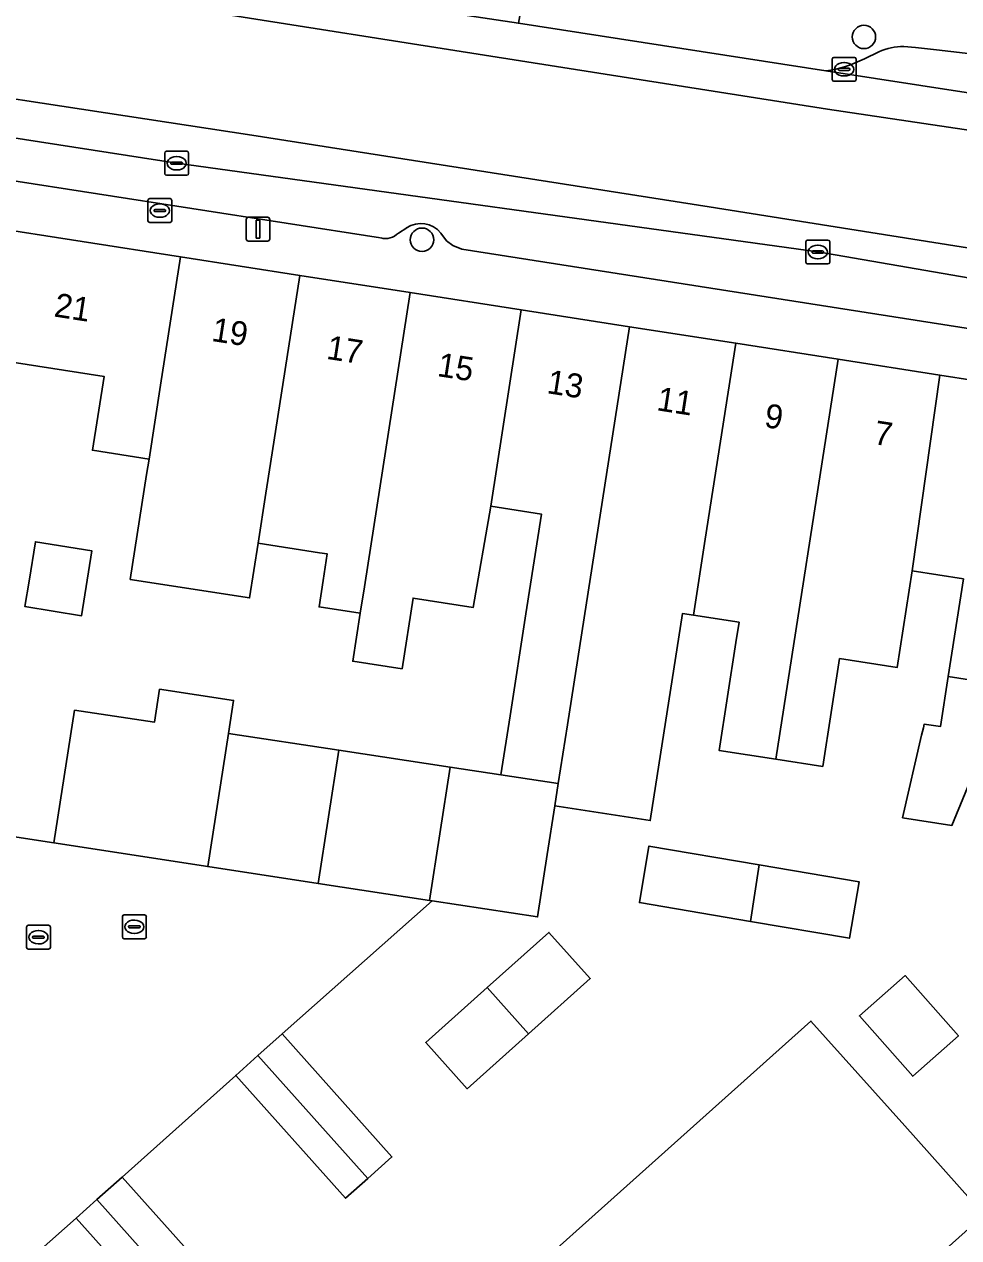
# Model space of a CAD drawing. Extents: x 162172 to 163187, y 382874 to 383685.
# Drawn here: x 162633.7 to 162672.8, y 383280.9 to 383331.7 of the extents above; entities that cross this region are included whole.
import ezdxf

# ---------------------------------------------------------------- set-up
doc = ezdxf.new("R2010")
doc.units = 0
for name, color, linetype in [('IMGEO_Boom', 7, 'Continuous'), ('IMGEO_Brandkraan', 7, 'Continuous'), ('IMGEO_Erf', 7, 'Continuous'), ('IMGEO_Kolk', 7, 'Continuous'), ('IMGEO_Lichtmast', 7, 'Continuous'), ('IMGEO_Pand', 7, 'Continuous'), ('IMGEO_Pand_nummerreeks', 7, 'Continuous'), ('IMGEO_Parkeervlak_open', 7, 'Continuous'), ('IMGEO_Rijbaan_lokaal_gesloten', 7, 'Continuous'), ('IMGEO_Rijbaan_lokaal_open', 7, 'Continuous'), ('IMGEO_Rioolput', 7, 'Continuous'), ('IMGEO_Voetpad_open', 7, 'Continuous')]:
    doc.layers.add(name, color=color, linetype=linetype)

msp = doc.modelspace()

# ---------------------------------------------------------------- linework, layer by layer
at = {"layer": 'IMGEO_Boom'}
for centre in [(162668.827, 383331.156), (162650.322, 383322.668)]:
    msp.add_circle(centre, 0.489, dxfattribs=at)
at = {"layer": 'IMGEO_Brandkraan'}
for p, q in [((162638.844, 383323.463), (162638.844, 383324.315)), ((162638.919, 383324.389), (162639.771, 383324.389)), ((162639.332, 383324.169), (162639.357, 383324.169)), ((162639.845, 383324.315), (162639.845, 383323.463)), ((162639.103, 383323.883), (162639.103, 383323.895)), ((162639.541, 383323.846), (162639.143, 383323.846)), ((162639.146, 383323.932), (162639.544, 383323.932)), ((162639.587, 383323.895), (162639.587, 383323.883)), ((162639.771, 383323.389), (162638.919, 383323.389)), ((162639.355, 383323.609), (162639.33, 383323.609))]:
    msp.add_line(p, q, dxfattribs=at)
for points in [[(162638.844, 383323.463), (162638.844, 383324.315)], [(162638.919, 383324.389), (162639.771, 383324.389)], [(162639.845, 383324.315), (162639.845, 383323.463)], [(162639.771, 383323.389), (162638.919, 383323.389)]]:
    msp.add_lwpolyline(points, dxfattribs=at)
for centre, radius, start, end in [((162638.921, 383324.313), 0.0765, 91.552, 178.448), ((162638.921, 383324.313), 0.0765, 91.552, 178.448), ((162639.769, 383324.313), 0.0765, 1.552, 88.448), ((162639.769, 383324.313), 0.0765, 1.552, 88.448), ((162639.143, 383323.892), 0.0403, 85.8775, 175.7526), ((162639.14, 383323.882), 0.0366, 178.938, 274.7102), ((162639.544, 383323.889), 0.043, 264.8664, 352.4533), ((162639.548, 383323.894), 0.0386, 1.7309, 96.639), ((162638.921, 383323.465), 0.0765, 181.552, 268.448), ((162638.921, 383323.465), 0.0765, 181.552, 268.448), ((162639.769, 383323.465), 0.0765, 271.552, 358.448), ((162639.769, 383323.465), 0.0765, 271.552, 358.448)]:
    msp.add_arc(centre, radius, start, end, dxfattribs=at)
for centre, major_axis, ratio, start_param, end_param in [((162639.331, 383323.889), (-0.387, 0.002), 0.722429, 4.712389, 7.853982), ((162639.356, 383323.889), (-0.39, 0.002), 0.717154, 1.570796, 4.712389)]:
    msp.add_ellipse(centre, major_axis=major_axis, ratio=ratio, start_param=start_param, end_param=end_param, dxfattribs=at)
at = {"layer": 'IMGEO_Erf'}
for points in [[(162631.523, 383297.936), (162634.907, 383297.419), (162635.772, 383302.977), (162639.117, 383302.47), (162639.333, 383303.854), (162642.432, 383303.384), (162642.217, 383302), (162646.844, 383301.3), (162651.499, 383300.594), (162653.623, 383300.272), (162654.007, 383302.742), (162654.672, 383307.015), (162655.321, 383311.187), (162653.2, 383311.517), (162652.468, 383307.28), (162649.948, 383307.672), (162649.487, 383304.708), (162647.425, 383305.028), (162647.737, 383307.034), (162646.012, 383307.303), (162646.183, 383308.404), (162646.357, 383309.517), (162646.024, 383309.569), (162643.457, 383309.968), (162643.1, 383307.674), (162638.109, 383308.451), (162638.792, 383312.839), (162638.892, 383313.48), (162636.521, 383313.858), (162637.013, 383316.947), (162632.069, 383317.716)], [(162674.08, 383301.973), (162672.512, 383298.155), (162670.441, 383298.478), (162671.243, 383301.926), (162671.316, 383302.239), (162671.353, 383302.398), (162672.027, 383302.293), (162672.353, 383304.387), (162672.989, 383308.47), (162670.841, 383308.804), (162670.213, 383304.762), (162667.807, 383305.136), (162667.105, 383300.621), (162665.136, 383300.927), (162662.764, 383301.296), (162663.466, 383305.811), (162663.598, 383306.659), (162661.683, 383306.957), (162661.23, 383307.027), (162659.878, 383298.358), (162655.881, 383298.979), (162655.569, 383296.943), (162655.162, 383294.323), (162650.75, 383294.997), (162644.466, 383289.424), (162649.063, 383284.282), (162648.053, 383283.379), (162647.121, 383282.545), (162642.523, 383287.687), (162637.762, 383283.434), (162642.37, 383278.28)], [(162640.451, 383276.564), (162635.843, 383281.717), (162632.163, 383278.465)]]:
    msp.add_lwpolyline(points, dxfattribs=at)
for points in [[(162633.867, 383308.374), (162634.137, 383310.028), (162636.504, 383309.641), (162636.06, 383306.924), (162633.694, 383307.311)], [(162659.426, 383294.924), (162659.826, 383297.287), (162664.446, 383296.504), (162668.621, 383295.797), (162668.221, 383293.434), (162664.076, 383294.136)], [(162657.367, 383291.74), (162654.784, 383289.43), (162652.212, 383287.13), (162650.478, 383289.068), (162653.05, 383291.368), (162655.633, 383293.678)], [(162668.637, 383290.177), (162670.546, 383291.87), (162672.78, 383289.35), (162670.871, 383287.657)], [(162666.609, 383289.967), (162670.532, 383285.58), (162673.865, 383281.853), (162650.074, 383260.577), (162642.818, 383268.691), (162646.546, 383272.025)]]:
    msp.add_lwpolyline(points, close=True, dxfattribs=at)
at = {"layer": 'IMGEO_Kolk'}
for p, q in [((162667.572, 383330.302), (162668.424, 383330.302)), ((162667.497, 383329.376), (162667.497, 383330.228)), ((162667.756, 383329.796), (162667.756, 383329.808)), ((162668.194, 383329.759), (162667.796, 383329.759)), ((162667.799, 383329.845), (162668.197, 383329.845)), ((162667.985, 383330.082), (162668.01, 383330.082)), ((162668.24, 383329.808), (162668.24, 383329.796)), ((162668.498, 383330.228), (162668.498, 383329.376)), ((162668.424, 383329.302), (162667.572, 383329.302)), ((162668.008, 383329.522), (162667.983, 383329.522)), ((162639.549, 383325.443), (162639.549, 383326.295)), ((162639.624, 383326.369), (162640.476, 383326.369)), ((162640.55, 383326.295), (162640.55, 383325.443)), ((162639.808, 383325.863), (162639.808, 383325.875)), ((162640.246, 383325.826), (162639.848, 383325.826)), ((162639.851, 383325.912), (162640.249, 383325.912)), ((162640.037, 383326.149), (162640.062, 383326.149)), ((162640.292, 383325.875), (162640.292, 383325.863)), ((162640.476, 383325.369), (162639.624, 383325.369)), ((162640.06, 383325.589), (162640.035, 383325.589)), ((162666.469, 383322.655), (162667.321, 383322.655)), ((162666.394, 383321.729), (162666.394, 383322.581)), ((162666.653, 383322.149), (162666.653, 383322.161)), ((162667.091, 383322.112), (162666.693, 383322.112)), ((162666.696, 383322.198), (162667.094, 383322.198)), ((162666.882, 383322.435), (162666.907, 383322.435)), ((162667.137, 383322.161), (162667.137, 383322.149)), ((162667.395, 383322.581), (162667.395, 383321.729)), ((162667.321, 383321.655), (162666.469, 383321.655)), ((162666.905, 383321.875), (162666.88, 383321.875)), ((162637.778, 383293.485), (162637.778, 383294.337)), ((162637.853, 383294.411), (162638.705, 383294.411)), ((162638.266, 383294.191), (162638.291, 383294.191)), ((162638.779, 383294.337), (162638.779, 383293.485)), ((162638.037, 383293.905), (162638.037, 383293.917)), ((162638.475, 383293.868), (162638.077, 383293.868)), ((162638.08, 383293.954), (162638.478, 383293.954)), ((162638.521, 383293.917), (162638.521, 383293.905)), ((162638.705, 383293.411), (162637.853, 383293.411)), ((162638.289, 383293.631), (162638.264, 383293.631))]:
    msp.add_line(p, q, dxfattribs=at)
for points in [[(162667.572, 383330.302), (162668.424, 383330.302)], [(162667.497, 383329.376), (162667.497, 383330.228)], [(162668.498, 383330.228), (162668.498, 383329.376)], [(162668.424, 383329.302), (162667.572, 383329.302)], [(162639.549, 383325.443), (162639.549, 383326.295)], [(162639.624, 383326.369), (162640.476, 383326.369)], [(162640.55, 383326.295), (162640.55, 383325.443)], [(162640.476, 383325.369), (162639.624, 383325.369)], [(162666.469, 383322.655), (162667.321, 383322.655)], [(162666.394, 383321.729), (162666.394, 383322.581)], [(162667.395, 383322.581), (162667.395, 383321.729)], [(162667.321, 383321.655), (162666.469, 383321.655)], [(162637.778, 383293.485), (162637.778, 383294.337)], [(162637.853, 383294.411), (162638.705, 383294.411)], [(162638.779, 383294.337), (162638.779, 383293.485)], [(162638.705, 383293.411), (162637.853, 383293.411)]]:
    msp.add_lwpolyline(points, dxfattribs=at)
for centre, radius, start, end in [((162667.574, 383330.226), 0.0765, 91.552, 178.448), ((162667.574, 383330.226), 0.0765, 91.552, 178.448), ((162668.422, 383330.226), 0.0765, 1.552, 88.448), ((162668.422, 383330.226), 0.0765, 1.552, 88.448), ((162667.796, 383329.805), 0.0403, 85.8775, 175.7526), ((162667.793, 383329.795), 0.0366, 178.938, 274.7102), ((162668.197, 383329.802), 0.043, 264.8664, 352.4533), ((162668.201, 383329.807), 0.0386, 1.7309, 96.639), ((162667.574, 383329.378), 0.0765, 181.552, 268.448), ((162667.574, 383329.378), 0.0765, 181.552, 268.448), ((162668.422, 383329.378), 0.0765, 271.552, 358.448), ((162668.422, 383329.378), 0.0765, 271.552, 358.448), ((162639.626, 383326.293), 0.0765, 91.552, 178.448), ((162639.626, 383326.293), 0.0765, 91.552, 178.448), ((162640.474, 383326.293), 0.0765, 1.552, 88.448), ((162640.474, 383326.293), 0.0765, 1.552, 88.448), ((162639.848, 383325.872), 0.0403, 85.8775, 175.7526), ((162639.845, 383325.862), 0.0366, 178.938, 274.7102), ((162640.249, 383325.869), 0.043, 264.8664, 352.4533), ((162640.253, 383325.874), 0.0386, 1.7309, 96.639), ((162639.626, 383325.445), 0.0765, 181.552, 268.448), ((162639.626, 383325.445), 0.0765, 181.552, 268.448), ((162640.474, 383325.445), 0.0765, 271.552, 358.448), ((162640.474, 383325.445), 0.0765, 271.552, 358.448), ((162666.471, 383322.579), 0.0765, 91.552, 178.448), ((162666.471, 383322.579), 0.0765, 91.552, 178.448), ((162667.319, 383322.579), 0.0765, 1.552, 88.448), ((162667.319, 383322.579), 0.0765, 1.552, 88.448), ((162666.693, 383322.158), 0.0403, 85.8775, 175.7526), ((162666.69, 383322.148), 0.0366, 178.938, 274.7102), ((162667.094, 383322.155), 0.043, 264.8664, 352.4533), ((162667.098, 383322.16), 0.0386, 1.7309, 96.639), ((162666.471, 383321.731), 0.0765, 181.552, 268.448), ((162666.471, 383321.731), 0.0765, 181.552, 268.448), ((162667.319, 383321.731), 0.0765, 271.552, 358.448), ((162667.319, 383321.731), 0.0765, 271.552, 358.448), ((162637.855, 383294.335), 0.0765, 91.552, 178.448), ((162637.855, 383294.335), 0.0765, 91.552, 178.448), ((162638.703, 383294.335), 0.0765, 1.552, 88.448), ((162638.703, 383294.335), 0.0765, 1.552, 88.448), ((162638.077, 383293.914), 0.0403, 85.8775, 175.7526), ((162638.074, 383293.904), 0.0366, 178.938, 274.7102), ((162638.478, 383293.911), 0.043, 264.8664, 352.4533), ((162638.482, 383293.916), 0.0386, 1.7309, 96.639), ((162637.855, 383293.487), 0.0765, 181.552, 268.448), ((162637.855, 383293.487), 0.0765, 181.552, 268.448), ((162638.703, 383293.487), 0.0765, 271.552, 358.448), ((162638.703, 383293.487), 0.0765, 271.552, 358.448)]:
    msp.add_arc(centre, radius, start, end, dxfattribs=at)
for centre, major_axis, ratio, start_param, end_param in [((162667.984, 383329.802), (-0.387, 0.002), 0.722429, 4.712389, 7.853982), ((162668.009, 383329.802), (-0.39, 0.002), 0.717154, 1.570796, 4.712389), ((162640.036, 383325.869), (-0.387, 0.002), 0.722429, 4.712389, 7.853982), ((162640.061, 383325.869), (-0.39, 0.002), 0.717154, 1.570796, 4.712389), ((162666.881, 383322.155), (-0.387, 0.002), 0.722429, 4.712389, 7.853982), ((162666.906, 383322.155), (-0.39, 0.002), 0.717154, 1.570796, 4.712389), ((162638.265, 383293.911), (-0.387, 0.002), 0.722429, 4.712389, 7.853982), ((162638.29, 383293.911), (-0.39, 0.002), 0.717154, 1.570796, 4.712389)]:
    msp.add_ellipse(centre, major_axis=major_axis, ratio=ratio, start_param=start_param, end_param=end_param, dxfattribs=at)
at = {"layer": 'IMGEO_Lichtmast'}
for p, q in [((162642.959, 383322.71), (162642.959, 383323.51)), ((162642.959, 383323.51), (162642.959, 383322.71)), ((162643.059, 383323.61), (162643.849, 383323.61)), ((162643.849, 383323.61), (162643.059, 383323.61)), ((162643.949, 383323.51), (162643.949, 383322.71)), ((162643.949, 383322.71), (162643.949, 383323.51)), ((162643.849, 383322.61), (162643.059, 383322.61)), ((162643.059, 383322.61), (162643.849, 383322.61))]:
    msp.add_line(p, q, dxfattribs=at)
msp.add_lwpolyline([(162643.379, 383323.485), (162643.529, 383323.485), (162643.529, 383322.735), (162643.379, 383322.735), (162643.379, 383323.485)], dxfattribs=at)
for centre, start, end in [((162643.059, 383323.51), 90, 180), ((162643.059, 383323.51), 90, 180), ((162643.849, 383323.51), 0, 90), ((162643.849, 383323.51), 360, 90), ((162643.059, 383322.71), 180, 270), ((162643.059, 383322.71), 180, 270), ((162643.849, 383322.71), 270, 0), ((162643.849, 383322.71), 270, 0)]:
    msp.add_arc(centre, 0.1, start, end, dxfattribs=at)
at = {"layer": 'IMGEO_Pand'}
for points in [[(162640.21, 383321.951), (162631.965, 383323.234), (162631.649, 383323.283), (162630.867, 383317.903), (162631.183, 383317.854), (162632.069, 383317.716), (162637.013, 383316.947), (162636.521, 383313.858), (162638.892, 383313.48), (162639.374, 383316.579)], [(162645.201, 383321.175), (162640.21, 383321.951), (162639.374, 383316.579), (162638.892, 383313.48), (162638.792, 383312.839), (162638.109, 383308.451), (162643.1, 383307.674), (162643.457, 383309.968), (162643.783, 383312.062), (162643.976, 383313.301)], [(162649.828, 383320.455), (162645.201, 383321.175), (162643.976, 383313.301), (162643.783, 383312.062), (162643.457, 383309.968), (162646.024, 383309.569), (162646.357, 383309.517), (162646.183, 383308.404), (162646.012, 383307.303), (162647.737, 383307.034), (162647.909, 383308.136)], [(162654.479, 383319.731), (162649.828, 383320.455), (162647.909, 383308.136), (162647.737, 383307.034), (162647.425, 383305.028), (162649.487, 383304.708), (162649.948, 383307.672), (162652.468, 383307.28), (162653.2, 383311.517)], [(162659.009, 383319.026), (162654.479, 383319.731), (162653.2, 383311.517), (162655.321, 383311.187), (162654.672, 383307.015), (162654.007, 383302.742), (162653.623, 383300.272), (162656.023, 383299.909), (162656.415, 383302.367)], [(162662.178, 383310.134), (162663.456, 383318.334), (162659.009, 383319.026), (162656.415, 383302.367), (162656.023, 383299.909), (162655.881, 383298.979), (162659.878, 383298.358), (162661.23, 383307.027), (162661.683, 383306.957)], [(162665.136, 383300.927), (162667.748, 383317.667), (162663.456, 383318.334), (162662.178, 383310.134), (162661.683, 383306.957), (162663.598, 383306.659), (162663.466, 383305.811), (162662.764, 383301.296)], [(162665.136, 383300.927), (162667.105, 383300.621), (162667.807, 383305.136), (162670.213, 383304.762), (162670.841, 383308.804), (162672.001, 383317.005), (162667.748, 383317.667)], [(162676.322, 383316.333), (162672.001, 383317.005), (162670.841, 383308.804), (162672.989, 383308.47), (162672.353, 383304.387), (162674.407, 383304.066)], [(162633.867, 383308.374), (162633.694, 383307.311), (162636.06, 383306.924), (162636.504, 383309.641), (162634.137, 383310.028)], [(162674.109, 383302.16), (162674.407, 383304.066), (162672.353, 383304.387), (162672.027, 383302.293), (162671.353, 383302.398), (162671.316, 383302.239), (162671.243, 383301.926), (162670.441, 383298.478), (162672.512, 383298.155), (162674.08, 383301.973)], [(162642.217, 383302), (162642.432, 383303.384), (162639.333, 383303.854), (162639.117, 383302.47), (162635.772, 383302.977), (162634.907, 383297.419), (162641.351, 383296.434)], [(162645.976, 383295.727), (162646.844, 383301.3), (162642.217, 383302), (162641.351, 383296.434)], [(162650.631, 383295.015), (162651.499, 383300.594), (162646.844, 383301.3), (162645.976, 383295.727)], [(162655.881, 383298.979), (162656.023, 383299.909), (162653.623, 383300.272), (162651.499, 383300.594), (162650.631, 383295.015), (162650.75, 383294.997), (162655.162, 383294.323), (162655.569, 383296.943)], [(162664.446, 383296.504), (162659.826, 383297.287), (162659.426, 383294.924), (162664.076, 383294.136)], [(162664.076, 383294.136), (162668.221, 383293.434), (162668.621, 383295.797), (162664.446, 383296.504)], [(162654.784, 383289.43), (162657.367, 383291.74), (162655.633, 383293.678), (162653.05, 383291.368)], [(162670.871, 383287.657), (162672.78, 383289.35), (162670.546, 383291.87), (162668.637, 383290.177)], [(162654.784, 383289.43), (162653.05, 383291.368), (162650.478, 383289.068), (162652.212, 383287.13)], [(162670.532, 383285.58), (162666.609, 383289.967), (162646.546, 383272.025), (162642.818, 383268.691), (162650.074, 383260.577), (162673.865, 383281.853)], [(162643.454, 383288.52), (162648.053, 383283.379), (162649.063, 383284.282), (162644.466, 383289.424)], [(162643.454, 383288.52), (162642.523, 383287.687), (162647.121, 383282.545), (162648.053, 383283.379)], [(162636.707, 383282.49), (162641.316, 383277.338), (162642.37, 383278.28), (162637.762, 383283.434)], [(162636.707, 383282.49), (162635.843, 383281.717), (162640.451, 383276.564), (162641.316, 383277.338)]]:
    msp.add_lwpolyline(points, close=True, dxfattribs=at)
at = {"layer": 'IMGEO_Parkeervlak_open'}
for points in [[(162681.525, 383329.352), (162678.105, 383329.885), (162671.858, 383330.613), (162670.982, 383330.717), (162670.498, 383330.752)], [(162669.456, 383330.536), (162668.843, 383330.245)], [(162694.423, 383317.323), (162690.471, 383318.089), (162666.895, 383322.156), (162640.05, 383325.87), (162617.849, 383329.326), (162614.538, 383329.866)], [(162667.234, 383329.74), (162695.256, 383325.416)], [(162632.784, 383325.209), (162648.591, 383322.748)], [(162649.335, 383322.95), (162649.68, 383323.161)], [(162651.106, 383322.943), (162651.352, 383322.618), (162651.606, 383322.432), (162651.984, 383322.267), (162675.159, 383318.642), (162675.566, 383318.718), (162675.894, 383318.855), (162676.175, 383319.078)]]:
    msp.add_lwpolyline(points, dxfattribs=at)
for centre, radius, start, end in [((162670.427, 383328.472), 2.281, 88.221, 115.2013), ((162666.579, 383334.644), 4.948, 277.6126, 297.2373), ((162650.278, 383322.303), 1.046, 37.7242, 124.8922), ((162648.795, 383323.469), 0.749, 254.2345, 316.1453)]:
    msp.add_arc(centre, radius, start, end, dxfattribs=at)
at = {"layer": 'IMGEO_Rijbaan_lokaal_gesloten'}
for points in [[(162701.209, 383324.364), (162695.256, 383325.416), (162667.234, 383329.74), (162654.358, 383331.729), (162650.713, 383332.282), (162613.69, 383338.058), (162613.319, 383338.115), (162605.204, 383339.371), (162601.788, 383339.9), (162574.971, 383344.078), (162574.184, 383344.194), (162573.598, 383344.329), (162573.305, 383344.396)], [(162572.334, 383336.354), (162582.593, 383334.79), (162596.519, 383332.638), (162599.695, 383332.15), (162604.062, 383331.476), (162608.129, 383330.849), (162614.538, 383329.866), (162617.849, 383329.326), (162640.05, 383325.87), (162666.895, 383322.156), (162690.471, 383318.089), (162694.423, 383317.323)], [(162759.102, 383279.436), (162751.245, 383288.934), (162744.614, 383296.969), (162741.887, 383300.164), (162738.772, 383303.437), (162735.656, 383306.164), (162728.412, 383311.307), (162722.803, 383314.892), (162719.766, 383316.606), (162716.105, 383318.242), (162707.381, 383321.359), (162706.089, 383321.777), (162704.23, 383322.378), (162698.267, 383323.385), (162686.155, 383325.334), (162667.305, 383328.139), (162627.21, 383334.45)], [(162627.21, 383334.45), (162667.305, 383328.139), (162686.155, 383325.334), (162698.267, 383323.385), (162704.23, 383322.378), (162706.089, 383321.777), (162707.381, 383321.359), (162716.105, 383318.242), (162719.766, 383316.606), (162722.803, 383314.892), (162728.412, 383311.307), (162735.656, 383306.164), (162738.772, 383303.437), (162741.887, 383300.164), (162744.614, 383296.969), (162751.245, 383288.934), (162759.102, 383279.436)], [(162707.088, 383314.928), (162701.541, 383316.806), (162700.737, 383317.078), (162700.292, 383317.242), (162697.78, 383318.084), (162693.028, 383319.097), (162684.675, 383320.5), (162662.339, 383324.046), (162643.197, 383327.047), (162623.802, 383330.008)], [(162623.802, 383330.008), (162643.197, 383327.047), (162662.339, 383324.046), (162684.675, 383320.5), (162693.028, 383319.097), (162697.78, 383318.084), (162700.292, 383317.242), (162700.737, 383317.078), (162701.541, 383316.806), (162707.088, 383314.928), (162713.047, 383312.279), (162718.051, 383309.824), (162725.217, 383305.07), (162729.268, 383302.265), (162732.618, 383299.46), (162735.188, 383297.122), (162737.681, 383294.706), (162741.264, 383290.81), (162746.988, 383284.773), (162754.973, 383275.848)]]:
    msp.add_lwpolyline(points, dxfattribs=at)
at = {"layer": 'IMGEO_Rijbaan_lokaal_open'}
msp.add_lwpolyline([(162632.163, 383278.465), (162635.843, 383281.717), (162636.707, 383282.49), (162637.762, 383283.434), (162642.523, 383287.687), (162643.454, 383288.52), (162644.466, 383289.424), (162650.75, 383294.997), (162650.631, 383295.015), (162645.976, 383295.727), (162641.351, 383296.434), (162634.907, 383297.419), (162631.523, 383297.936)], dxfattribs=at)
at = {"layer": 'IMGEO_Rioolput'}
for p, q in [((162633.76, 383293.048), (162633.76, 383293.9)), ((162633.835, 383293.974), (162634.687, 383293.974)), ((162634.248, 383293.754), (162634.273, 383293.754)), ((162634.761, 383293.9), (162634.761, 383293.048)), ((162634.019, 383293.468), (162634.019, 383293.48)), ((162634.457, 383293.431), (162634.059, 383293.431)), ((162634.062, 383293.517), (162634.46, 383293.517)), ((162634.271, 383293.194), (162634.246, 383293.194)), ((162634.503, 383293.48), (162634.503, 383293.468)), ((162634.687, 383292.974), (162633.835, 383292.974))]:
    msp.add_line(p, q, dxfattribs=at)
for points in [[(162633.76, 383293.048), (162633.76, 383293.9)], [(162633.835, 383293.974), (162634.687, 383293.974)], [(162634.761, 383293.9), (162634.761, 383293.048)], [(162634.687, 383292.974), (162633.835, 383292.974)]]:
    msp.add_lwpolyline(points, dxfattribs=at)
for centre, radius, start, end in [((162633.837, 383293.898), 0.0765, 91.552, 178.448), ((162633.837, 383293.898), 0.0765, 91.552, 178.448), ((162634.685, 383293.898), 0.0765, 1.552, 88.448), ((162634.685, 383293.898), 0.0765, 1.552, 88.448), ((162634.059, 383293.477), 0.0403, 85.8775, 175.7526), ((162634.056, 383293.467), 0.0366, 178.938, 274.7102), ((162634.46, 383293.474), 0.043, 264.8664, 352.4533), ((162634.464, 383293.479), 0.0386, 1.7309, 96.639), ((162633.837, 383293.05), 0.0765, 181.552, 268.448), ((162633.837, 383293.05), 0.0765, 181.552, 268.448), ((162634.685, 383293.05), 0.0765, 271.552, 358.448), ((162634.685, 383293.05), 0.0765, 271.552, 358.448)]:
    msp.add_arc(centre, radius, start, end, dxfattribs=at)
for centre, major_axis, ratio, start_param, end_param in [((162634.247, 383293.474), (-0.387, 0.002), 0.722429, 4.712389, 7.853982), ((162634.272, 383293.474), (-0.39, 0.002), 0.717154, 1.570796, 4.712389)]:
    msp.add_ellipse(centre, major_axis=major_axis, ratio=ratio, start_param=start_param, end_param=end_param, dxfattribs=at)
at = {"layer": 'IMGEO_Voetpad_open'}
for points in [[(162650.594, 383332.335), (162650.713, 383332.282), (162650.798, 383332.721), (162654.447, 383332.19), (162654.358, 383331.729), (162667.234, 383329.74)], [(162670.498, 383330.752), (162670.982, 383330.717), (162671.858, 383330.613), (162678.105, 383329.885), (162681.525, 383329.352)], [(162668.843, 383330.245), (162669.456, 383330.536)], [(162648.591, 383322.748), (162632.784, 383325.209)], [(162631.965, 383323.234), (162640.21, 383321.951), (162645.201, 383321.175), (162649.828, 383320.455), (162654.479, 383319.731), (162659.009, 383319.026), (162663.456, 383318.334), (162667.748, 383317.667), (162672.001, 383317.005), (162676.322, 383316.333), (162681.42, 383315.54), (162689.258, 383314.32), (162698.021, 383312.957), (162709.798, 383310.749)], [(162649.68, 383323.161), (162649.335, 383322.95)], [(162676.175, 383319.078), (162675.894, 383318.855), (162675.566, 383318.718), (162675.159, 383318.642), (162651.984, 383322.267), (162651.606, 383322.432), (162651.352, 383322.618), (162651.106, 383322.943)]]:
    msp.add_lwpolyline(points, dxfattribs=at)
for centre, radius, start, end in [((162670.427, 383328.472), 2.281, 88.221, 115.2013), ((162666.579, 383334.644), 4.948, 277.6126, 297.2373), ((162650.278, 383322.303), 1.046, 37.7242, 124.8922), ((162648.795, 383323.469), 0.749, 254.2345, 316.1453)]:
    msp.add_arc(centre, radius, start, end, dxfattribs=at)

# ---------------------------------------------------------------- texts
at = {"layer": 'IMGEO_Pand_nummerreeks'}
for s, rotation, p in [('21', 351.1535, (162634.879, 383319.46)), ('19', 351.165, (162641.475, 383318.435)), ('17', 351.1535, (162646.287, 383317.687)), ('15', 351.1535, (162650.926, 383316.965)), ('13', 351.1535, (162655.516, 383316.25)), ('11', 351.1535, (162660.114, 383315.535)), ('9', 351.1561, (162664.618, 383314.833)), ('7', 351.1561, (162669.197, 383314.121))]:
    msp.add_text(s, height=1, rotation=rotation, dxfattribs=at).set_placement(p)

doc.saveas('drawing.dxf')
